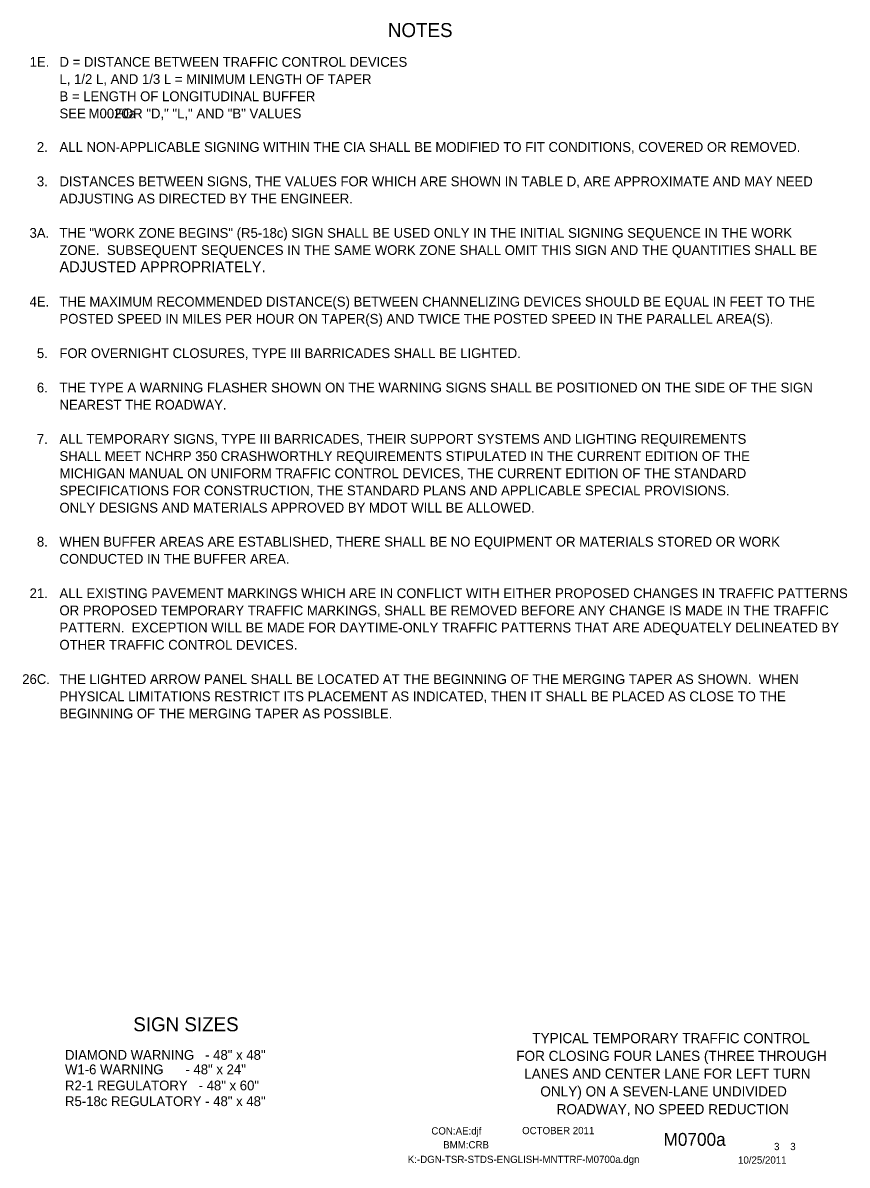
# Model space of a CAD drawing. Extents: x 16038 to 19504, y 5920 to 8321.
# Drawn here: x 18799 to 19504, y 7218 to 8195 of the extents above; entities that cross this region are included whole.
import ezdxf

# ---------------------------------------------------------------- set-up
doc = ezdxf.new("R2010")
doc.units = 0
for name, color, linetype in [('BORDER', 7, 'Continuous'), ('BORDER_SIGNAL_WO', 7, 'Continuous'), ('TYPICAL_TEXT_DIMEN_PR', 7, 'Continuous')]:
    doc.layers.add(name, color=color, linetype=linetype)

msp = doc.modelspace()

# ---------------------------------------------------------------- linework, layer by layer
at = {"layer": 'BORDER'}
for p, q in [((19347.25, 7297.5), (19347.25, 7297.5)), ((19347.25, 7297.5), (19347.25, 7297.5)), ((19347.25, 7291.25), (19347.25, 7291.25))]:
    msp.add_line(p, q, dxfattribs=at)

# ---------------------------------------------------------------- texts
for s, p in [('TYPICAL TEMPORARY TRAFFIC CONTROL', (19235.02, 7322.45)), ('FOR CLOSING FOUR LANES (THREE THROUGH', (19221.29, 7307.25)), ('LANES AND CENTER LANE FOR LEFT TURN', (19228.07, 7292.05)), ('ONLY) ON A SEVEN-LANE UNDIVIDED', (19241.91, 7276.85)), ('ROADWAY, NO SPEED REDUCTION', (19255.83, 7261.64))]:
    msp.add_text(s, height=8.6739, dxfattribs=at).set_placement(p)
at = {"layer": 'BORDER_SIGNAL_WO'}
for s, height, p in [('CON:AE:djf', 6.2, (19148.69, 7244.31)), ('    OCTOBER 2011    ', 6.2, (19217.08, 7244.59)), ('    M0700a   ', 11, (19330.86, 7234.63)), ('BMM:CRB   ', 6.2, (19158.81, 7232.42)), (' 3    3 ', 6.2, (19439.45, 7230.95)), ('K:-DGN-TSR-STDS-ENGLISH-MNTTRF-M0700a.dgn        ', 6.2, (19128.55, 7219.96)), ('10/25/2011    ', 6.2, (19410.93, 7219.38))]:
    msp.add_text(s, height=height, dxfattribs=at).set_placement(p)
at = {"layer": 'TYPICAL_TEXT_DIMEN_PR'}
for s, height, p in [('NOTES', 12, (19111.55, 8183.25)), ('1E.', 8.4, (18805.19, 8157.81)), ('D = DISTANCE BETWEEN TRAFFIC CONTROL DEVICES', 8.4, (18830.7, 8157.81)), ('L, 1/2 L, AND 1/3 L = MINIMUM LENGTH OF TAPER', 8.4, (18830.7, 8143.11)), ('B = LENGTH OF LONGITUDINAL BUFFER', 8.4, (18830.7, 8128.41)), ('SEE        FOR "D," "L," AND "B" VALUES', 8.4, (18830.7, 8113.71)), ('M0020a', 8.4, (18855.62, 8113.71)), ('2.', 8.4, (18811.39, 8085)), ('ALL NON-APPLICABLE SIGNING WITHIN THE CIA SHALL BE MODIFIED TO FIT CONDITIONS, COVERED OR REMOVED.', 8.4, (18830.7, 8085)), ('3.', 8.4, (18811.39, 8055.6)), ('DISTANCES BETWEEN SIGNS, THE VALUES FOR WHICH ARE SHOWN IN TABLE D, ARE APPROXIMATE AND MAY NEED', 8.4, (18830.7, 8055.6)), ('ADJUSTING AS DIRECTED BY THE ENGINEER.', 8.4, (18830.7, 8040.9)), ('3A.', 8.4, (18805.09, 8011.5)), ('THE "WORK ZONE BEGINS" (R5-18c) SIGN SHALL BE USED ONLY IN THE INITIAL SIGNING SEQUENCE IN THE WORK', 8.4, (18830.7, 8011.5)), ('ZONE.  SUBSEQUENT SEQUENCES IN THE SAME WORK ZONE SHALL OMIT THIS SIGN AND THE QUANTITIES SHALL BE', 8.4, (18830.7, 7996.8)), ('ADJUSTED APPROPRIATELY.', 9.3, (18830.7, 7982.1)), ('4E.', 8.4, (18805.13, 7952.7)), ('THE MAXIMUM RECOMMENDED DISTANCE(S) BETWEEN CHANNELIZING DEVICES SHOULD BE EQUAL IN FEET TO THE', 8.4, (18830.7, 7952.7)), ('POSTED SPEED IN MILES PER HOUR ON TAPER(S) AND TWICE THE POSTED SPEED IN THE PARALLEL AREA(S).', 8.4, (18830.7, 7938)), ('5.', 8.4, (18811.39, 7908.6)), ('FOR OVERNIGHT CLOSURES, TYPE III BARRICADES SHALL BE LIGHTED.', 8.4, (18830.7, 7908.6)), ('6.', 8.4, (18811.34, 7879.2)), ('THE TYPE A WARNING FLASHER SHOWN ON THE WARNING SIGNS SHALL BE POSITIONED ON THE SIDE OF THE SIGN', 8.4, (18830.7, 7879.2)), ('NEAREST THE ROADWAY.', 8.4, (18830.7, 7864.5)), ('7.', 8.4, (18811.34, 7835.23)), ('ALL TEMPORARY SIGNS, TYPE III BARRICADES, THEIR SUPPORT SYSTEMS AND LIGHTING REQUIREMENTS', 8.4, (18830.7, 7835.25)), ('SHALL MEET NCHRP 350 CRASHWORTHLY REQUIREMENTS STIPULATED IN THE CURRENT EDITION OF THE', 8.4, (18830.7, 7820.55)), ('MICHIGAN MANUAL ON UNIFORM TRAFFIC CONTROL DEVICES, THE CURRENT EDITION OF THE STANDARD', 8.4, (18830.7, 7805.85)), ('SPECIFICATIONS FOR CONSTRUCTION, THE STANDARD PLANS AND APPLICABLE SPECIAL PROVISIONS.', 8.4, (18830.7, 7791.15)), ('ONLY DESIGNS AND MATERIALS APPROVED BY MDOT WILL BE ALLOWED.', 8.4, (18830.7, 7776.45)), ('8.', 8.4, (18811.39, 7747.32)), ('WHEN BUFFER AREAS ARE ESTABLISHED, THERE SHALL BE NO EQUIPMENT OR MATERIALS STORED OR WORK     ', 8.4, (18830.7, 7747.32)), ('CONDUCTED IN THE BUFFER AREA.', 8.4, (18830.7, 7732.62)), ('21.', 8.4, (18805.14, 7703.22)), ('ALL EXISTING PAVEMENT MARKINGS WHICH ARE IN CONFLICT WITH EITHER PROPOSED CHANGES IN TRAFFIC PATTERNS', 8.4, (18830.7, 7703.22)), ('OR PROPOSED TEMPORARY TRAFFIC MARKINGS, SHALL BE REMOVED BEFORE ANY CHANGE IS MADE IN THE TRAFFIC', 8.4, (18830.7, 7688.52)), ('PATTERN.  EXCEPTION WILL BE MADE FOR DAYTIME-ONLY TRAFFIC PATTERNS THAT ARE ADEQUATELY DELINEATED BY', 8.4, (18830.7, 7673.82)), ('OTHER TRAFFIC CONTROL DEVICES.', 8.4, (18830.7, 7659.12)), ('26C.', 8.4, (18798.83, 7629.72)), ('THE LIGHTED ARROW PANEL SHALL BE LOCATED AT THE BEGINNING OF THE MERGING TAPER AS SHOWN.  WHEN', 8.4, (18830.7, 7629.72)), ('PHYSICAL LIMITATIONS RESTRICT ITS PLACEMENT AS INDICATED, THEN IT SHALL BE PLACED AS CLOSE TO THE', 8.4, (18830.7, 7615.02)), ('BEGINNING OF THE MERGING TAPER AS POSSIBLE.', 8.4, (18830.7, 7600.32)), ('SIGN SIZES', 12, (18893.83, 7332.62)), ('DIAMOND WARNING   - 48" x 48"', 8.4, (18835.45, 7308.22)), ('W1-6 WARNING      - 48" x 24"', 8.4, (18835.45, 7295.82)), ('R2-1 REGULATORY   - 48" x 60"', 8.4, (18835.45, 7282.08)), ('R5-18c REGULATORY - 48" x 48"', 8.4, (18835.45, 7268.63))]:
    msp.add_text(s, height=height, dxfattribs=at).set_placement(p)

doc.saveas('drawing.dxf')
